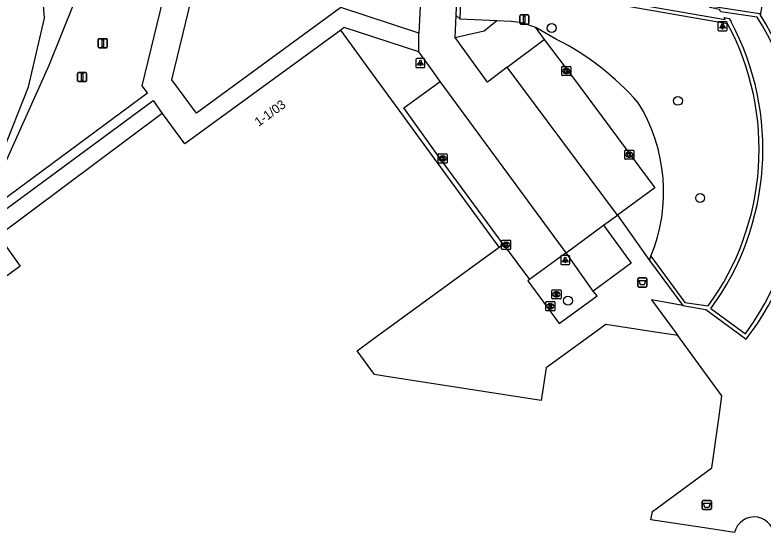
# Model space of a CAD drawing. Extents: x 161094 to 161705, y 379509 to 380907.
# Drawn here: x 161257.9 to 161340, y 380818.7 to 380876.1 of the extents above; entities that cross this region are included whole.
import ezdxf

# ---------------------------------------------------------------- set-up
doc = ezdxf.new("R2010")
doc.units = 0
for name, color, linetype in [('IMGEO_Afvalbak', 7, 'Continuous'), ('IMGEO_Boom', 7, 'Continuous'), ('IMGEO_Groenvoorziening', 7, 'Continuous'), ('IMGEO_Kolk', 7, 'Continuous'), ('IMGEO_Lichtpunt', 7, 'Continuous'), ('IMGEO_Muur', 7, 'Continuous'), ('IMGEO_Pand', 7, 'Continuous'), ('IMGEO_Pand_nummerreeks', 7, 'Continuous'), ('IMGEO_Parkeervlak_open', 7, 'Continuous'), ('IMGEO_Rijbaan_lokaal_open', 7, 'Continuous'), ('IMGEO_Rioolput', 7, 'Continuous'), ('IMGEO_Verkeersbordpaal', 7, 'Continuous'), ('IMGEO_Vlaggenmast', 7, 'Continuous'), ('IMGEO_Voetpad_open', 7, 'Continuous'), ('IMGEO_Waterloop', 7, 'Continuous')]:
    doc.layers.add(name, color=color, linetype=linetype)

msp = doc.modelspace()

# ---------------------------------------------------------------- linework, layer by layer
at = {"layer": 'IMGEO_Afvalbak'}
for p, q in [((161326.239, 380846.413), (161326.239, 380847.213)), ((161326.239, 380847.213), (161326.239, 380846.413)), ((161326.339, 380847.313), (161327.129, 380847.313)), ((161327.129, 380847.313), (161326.339, 380847.313)), ((161327.229, 380847.213), (161327.229, 380846.413)), ((161327.229, 380846.413), (161327.229, 380847.213)), ((161327.129, 380846.313), (161326.339, 380846.313)), ((161326.339, 380846.313), (161327.129, 380846.313)), ((161333.41, 380822.905), (161334.2, 380822.905)), ((161334.2, 380822.905), (161333.41, 380822.905)), ((161333.31, 380822.005), (161333.31, 380822.805)), ((161333.31, 380822.805), (161333.31, 380822.005)), ((161334.3, 380822.805), (161334.3, 380822.005)), ((161334.3, 380822.005), (161334.3, 380822.805)), ((161334.2, 380821.905), (161333.41, 380821.905)), ((161333.41, 380821.905), (161334.2, 380821.905))]:
    msp.add_line(p, q, dxfattribs=at)
for points in [[(161326.382, 380847.027), (161327.086, 380847.027), (161326.937, 380846.557), (161326.531, 380846.557), (161326.382, 380847.027)], [(161333.453, 380822.619), (161334.157, 380822.619), (161334.008, 380822.149), (161333.602, 380822.149), (161333.453, 380822.619)]]:
    msp.add_lwpolyline(points, dxfattribs=at)
for centre, start, end in [((161326.339, 380847.213), 90, 180), ((161326.339, 380847.213), 90, 180), ((161327.129, 380847.213), 0, 90), ((161327.129, 380847.213), 360, 90), ((161326.339, 380846.413), 180, 270), ((161326.339, 380846.413), 180, 270), ((161327.129, 380846.413), 270, 0), ((161327.129, 380846.413), 270, 0), ((161333.41, 380822.805), 90, 180), ((161333.41, 380822.805), 90, 180), ((161334.2, 380822.805), 0, 90), ((161334.2, 380822.805), 360, 90), ((161333.41, 380822.005), 180, 270), ((161333.41, 380822.005), 180, 270), ((161334.2, 380822.005), 270, 0), ((161334.2, 380822.005), 270, 0)]:
    msp.add_arc(centre, 0.1, start, end, dxfattribs=at)
at = {"layer": 'IMGEO_Boom'}
for centre in [(161316.783, 380874.712), (161330.632, 380866.728), (161333.071, 380856.073), (161318.568, 380844.809)]:
    msp.add_circle(centre, 0.489, dxfattribs=at)
at = {"layer": 'IMGEO_Groenvoorziening'}
for points in [[(161247.675, 380847.406), (161250.983, 380852.169), (161256.051, 380858.263), (161261.626, 380870.653), (161264.334, 380877.374), (161264.808, 380880.411), (161265.377, 380888.088)], [(161317.318, 380873.469), (161314.974, 380874.798)]]:
    msp.add_lwpolyline(points, dxfattribs=at)
for centre, radius, start, end in [((161303.829, 380846.829), 29.861, 41.23675, 63.14524), ((161310.537, 380856.742), 18.531, 337.61276, 31.81759)]:
    msp.add_arc(centre, radius, start, end, dxfattribs=at)
at = {"layer": 'IMGEO_Kolk'}
for p, q in [((161317.881, 380869.578), (161317.881, 380870.43)), ((161317.956, 380870.504), (161318.808, 380870.504)), ((161318.882, 380870.43), (161318.882, 380869.578)), ((161318.392, 380869.724), (161318.367, 380869.724)), ((161318.369, 380870.284), (161318.394, 380870.284)), ((161318.808, 380869.504), (161317.956, 380869.504)), ((161304.313, 380859.983), (161304.313, 380860.835)), ((161304.388, 380860.909), (161305.24, 380860.909)), ((161304.801, 380860.689), (161304.826, 380860.689)), ((161305.314, 380860.835), (161305.314, 380859.983)), ((161324.793, 380860.399), (161324.793, 380861.251)), ((161324.868, 380861.325), (161325.72, 380861.325)), ((161325.281, 380861.105), (161325.306, 380861.105)), ((161325.794, 380861.251), (161325.794, 380860.399)), ((161305.24, 380859.909), (161304.388, 380859.909)), ((161304.824, 380860.129), (161304.799, 380860.129)), ((161325.72, 380860.325), (161324.868, 380860.325)), ((161325.304, 380860.545), (161325.279, 380860.545)), ((161311.279, 380850.515), (161311.279, 380851.367)), ((161311.354, 380851.441), (161312.206, 380851.441)), ((161311.767, 380851.221), (161311.792, 380851.221)), ((161312.28, 380851.367), (161312.28, 380850.515)), ((161312.206, 380850.441), (161311.354, 380850.441)), ((161311.79, 380850.661), (161311.765, 380850.661))]:
    msp.add_line(p, q, dxfattribs=at)
for points in [[(161317.881, 380869.578), (161317.881, 380870.43)], [(161317.956, 380870.504), (161318.808, 380870.504)], [(161318.882, 380870.43), (161318.882, 380869.578)], [(161318.202, 380870.204), (161318.325, 380870.204), (161318.325, 380870.053), (161318.455, 380870.204), (161318.619, 380870.204), (161318.473, 380870.053), (161318.626, 380869.804), (161318.474, 380869.804), (161318.389, 380869.968), (161318.325, 380869.901), (161318.325, 380869.804), (161318.202, 380869.804), (161318.202, 380870.204)], [(161318.808, 380869.504), (161317.956, 380869.504)], [(161304.313, 380859.983), (161304.313, 380860.835)], [(161304.388, 380860.909), (161305.24, 380860.909)], [(161304.634, 380860.609), (161304.757, 380860.609), (161304.757, 380860.458), (161304.887, 380860.609), (161305.051, 380860.609), (161304.905, 380860.458), (161305.058, 380860.209), (161304.906, 380860.209), (161304.821, 380860.373), (161304.757, 380860.306), (161304.757, 380860.209), (161304.634, 380860.209), (161304.634, 380860.609)], [(161305.314, 380860.835), (161305.314, 380859.983)], [(161324.793, 380860.399), (161324.793, 380861.251)], [(161324.868, 380861.325), (161325.72, 380861.325)], [(161325.114, 380861.025), (161325.237, 380861.025), (161325.237, 380860.874), (161325.367, 380861.025), (161325.531, 380861.025), (161325.385, 380860.874), (161325.538, 380860.625), (161325.386, 380860.625), (161325.301, 380860.789), (161325.237, 380860.722), (161325.237, 380860.625), (161325.114, 380860.625), (161325.114, 380861.025)], [(161325.794, 380861.251), (161325.794, 380860.399)], [(161305.24, 380859.909), (161304.388, 380859.909)], [(161325.72, 380860.325), (161324.868, 380860.325)], [(161311.279, 380850.515), (161311.279, 380851.367)], [(161311.354, 380851.441), (161312.206, 380851.441)], [(161311.6, 380851.141), (161311.723, 380851.141), (161311.723, 380850.99), (161311.853, 380851.141), (161312.017, 380851.141), (161311.871, 380850.99), (161312.024, 380850.741), (161311.872, 380850.741), (161311.787, 380850.905), (161311.723, 380850.838), (161311.723, 380850.741), (161311.6, 380850.741), (161311.6, 380851.141)], [(161312.28, 380851.367), (161312.28, 380850.515)], [(161312.206, 380850.441), (161311.354, 380850.441)]]:
    msp.add_lwpolyline(points, dxfattribs=at)
for centre, start, end in [((161317.958, 380870.428), 91.55205, 178.44795), ((161317.958, 380870.428), 91.55205, 178.44795), ((161318.806, 380870.428), 1.55205, 88.44795), ((161318.806, 380870.428), 1.55205, 88.44795), ((161317.958, 380869.58), 181.55205, 268.44795), ((161317.958, 380869.58), 181.55205, 268.44795), ((161318.806, 380869.58), 271.55205, 358.44795), ((161318.806, 380869.58), 271.55205, 358.44795), ((161304.39, 380860.833), 91.55205, 178.44795), ((161304.39, 380860.833), 91.55205, 178.44795), ((161305.238, 380860.833), 1.55205, 88.44795), ((161305.238, 380860.833), 1.55205, 88.44795), ((161324.87, 380861.249), 91.55205, 178.44795), ((161324.87, 380861.249), 91.55205, 178.44795), ((161325.718, 380861.249), 1.55205, 88.44795), ((161325.718, 380861.249), 1.55205, 88.44795), ((161304.39, 380859.985), 181.55205, 268.44795), ((161304.39, 380859.985), 181.55205, 268.44795), ((161305.238, 380859.985), 271.55205, 358.44795), ((161305.238, 380859.985), 271.55205, 358.44795), ((161324.87, 380860.401), 181.55205, 268.44795), ((161324.87, 380860.401), 181.55205, 268.44795), ((161325.718, 380860.401), 271.55205, 358.44795), ((161325.718, 380860.401), 271.55205, 358.44795), ((161311.356, 380851.365), 91.55205, 178.44795), ((161311.356, 380851.365), 91.55205, 178.44795), ((161312.204, 380851.365), 1.55205, 88.44795), ((161312.204, 380851.365), 1.55205, 88.44795), ((161311.356, 380850.517), 181.55205, 268.44795), ((161311.356, 380850.517), 181.55205, 268.44795), ((161312.204, 380850.517), 271.55205, 358.44795), ((161312.204, 380850.517), 271.55205, 358.44795)]:
    msp.add_arc(centre, 0.0765, start, end, dxfattribs=at)
for centre, major_axis, ratio, start_param, end_param in [((161318.368, 380870.004), (-0.387, 0.002), 0.722429, 4.712389, 7.853982), ((161318.393, 380870.004), (-0.39, 0.002), 0.717154, 1.570796, 4.712389), ((161304.8, 380860.409), (-0.387, 0.002), 0.722429, 4.712389, 7.853982), ((161304.825, 380860.409), (-0.39, 0.002), 0.717154, 1.570796, 4.712389), ((161325.28, 380860.825), (-0.387, 0.002), 0.722429, 4.712389, 7.853982), ((161325.305, 380860.825), (-0.39, 0.002), 0.717154, 1.570796, 4.712389), ((161311.766, 380850.941), (-0.387, 0.002), 0.722429, 4.712389, 7.853982), ((161311.791, 380850.941), (-0.39, 0.002), 0.717154, 1.570796, 4.712389)]:
    msp.add_ellipse(centre, major_axis=major_axis, ratio=ratio, start_param=start_param, end_param=end_param, dxfattribs=at)
at = {"layer": 'IMGEO_Lichtpunt'}
for p, q in [((161335.928, 380875.411), (161335.12, 380875.411)), ((161335.928, 380875.411), (161335.12, 380875.411)), ((161335.026, 380875.316), (161335.026, 380874.509)), ((161335.026, 380875.316), (161335.026, 380874.509)), ((161336.022, 380874.509), (161336.022, 380875.316)), ((161336.022, 380874.509), (161336.022, 380875.316)), ((161335.12, 380874.415), (161335.928, 380874.415)), ((161335.12, 380874.415), (161335.928, 380874.415)), ((161301.874, 380871.278), (161301.874, 380870.471)), ((161301.874, 380871.278), (161301.874, 380870.471)), ((161302.776, 380871.373), (161301.968, 380871.373)), ((161302.776, 380871.373), (161301.968, 380871.373)), ((161302.87, 380870.471), (161302.87, 380871.278)), ((161302.87, 380870.471), (161302.87, 380871.278)), ((161301.968, 380870.377), (161302.776, 380870.377)), ((161301.968, 380870.377), (161302.776, 380870.377)), ((161317.768, 380849.682), (161317.768, 380848.875)), ((161317.768, 380849.682), (161317.768, 380848.875)), ((161318.67, 380849.777), (161317.862, 380849.777)), ((161318.67, 380849.777), (161317.862, 380849.777)), ((161318.764, 380848.875), (161318.764, 380849.682)), ((161318.764, 380848.875), (161318.764, 380849.682)), ((161317.862, 380848.781), (161318.67, 380848.781)), ((161317.862, 380848.781), (161318.67, 380848.781))]:
    msp.add_line(p, q, dxfattribs=at)
for points in [[(161335.4, 380874.98), (161335.439, 380874.952), (161335.251, 380874.69), (161335.213, 380874.717), (161335.4, 380874.98)], [(161335.502, 380874.932), (161335.549, 380874.932), (161335.549, 380874.61), (161335.502, 380874.61), (161335.502, 380874.932)], [(161335.612, 380874.952), (161335.65, 380874.979), (161335.837, 380874.717), (161335.798, 380874.689), (161335.612, 380874.952)], [(161302.248, 380870.942), (161302.287, 380870.914), (161302.099, 380870.652), (161302.061, 380870.679), (161302.248, 380870.942)], [(161302.35, 380870.894), (161302.397, 380870.894), (161302.397, 380870.572), (161302.35, 380870.572), (161302.35, 380870.894)], [(161302.46, 380870.914), (161302.498, 380870.941), (161302.685, 380870.679), (161302.646, 380870.651), (161302.46, 380870.914)], [(161318.142, 380849.346), (161318.181, 380849.318), (161317.993, 380849.056), (161317.955, 380849.083), (161318.142, 380849.346)], [(161318.244, 380849.298), (161318.291, 380849.298), (161318.291, 380848.976), (161318.244, 380848.976), (161318.244, 380849.298)], [(161318.354, 380849.318), (161318.392, 380849.345), (161318.579, 380849.083), (161318.54, 380849.055), (161318.354, 380849.318)]]:
    msp.add_lwpolyline(points, dxfattribs=at)
for centre in [(161335.525, 380875.114), (161302.373, 380871.076), (161318.267, 380849.48)]:
    msp.add_circle(centre, 0.0994, dxfattribs=at)
for centre, start, end in [((161335.12, 380875.316), 90, 180), ((161335.12, 380875.316), 90, 180), ((161335.928, 380875.316), 0, 90), ((161335.928, 380875.316), 0, 90), ((161335.12, 380874.509), 180, 270), ((161335.12, 380874.509), 180, 270), ((161335.928, 380874.509), 270, 0), ((161335.928, 380874.509), 270, 360), ((161301.968, 380871.278), 90, 180), ((161301.968, 380871.278), 90, 180), ((161302.776, 380871.278), 0, 90), ((161302.776, 380871.278), 0, 90), ((161301.968, 380870.471), 180, 270), ((161301.968, 380870.471), 180, 270), ((161302.776, 380870.471), 270, 0), ((161302.776, 380870.471), 270, 360), ((161317.862, 380849.682), 90, 180), ((161317.862, 380849.682), 90, 180), ((161318.67, 380849.682), 0, 90), ((161318.67, 380849.682), 0, 90), ((161317.862, 380848.875), 180, 270), ((161317.862, 380848.875), 180, 270), ((161318.67, 380848.875), 270, 0), ((161318.67, 380848.875), 270, 360)]:
    msp.add_arc(centre, 0.0946, start, end, dxfattribs=at)
at = {"layer": 'IMGEO_Muur'}
for points in [[(161306.292, 380876.085), (161306.491, 380880.768)], [(161306.491, 380880.768), (161335.834, 380875.644), (161335.707, 380875.861), (161336.242, 380875.775), (161336.471, 380875.384)], [(161336.089, 380875.176), (161306.872, 380880.312), (161306.694, 380875.729)], [(161339.327, 380875.911), (161335.345, 380876.499), (161335.189, 380876.739), (161334.122, 380876.951), (161334.149, 380877.149)], [(161334.149, 380877.149), (161339.598, 380876.315), (161339.698, 380876.139)], [(161306.292, 380876.085), (161306.694, 380875.729)], [(161327.526, 380849.234), (161327.672, 380849.684)], [(161327.526, 380849.234), (161331.183, 380844.292)], [(161327.672, 380849.684), (161331.402, 380844.627), (161333.951, 380844.232)], [(161331.183, 380844.292), (161333.696, 380843.835), (161338.134, 380840.611), (161339.389, 380842.344)], [(161334.256, 380843.966), (161338.044, 380841.191), (161338.993, 380842.577)]]:
    msp.add_lwpolyline(points, dxfattribs=at)
for centre, radius, start, end in [((161310.336, 380861.439), 29.623, 323.85249, 28.08204), ((161313.163, 380859.504), 30.882, 326.76115, 32.0907), ((161313.219, 380859.482), 31.283, 326.78041, 32.17187), ((161310.355, 380861.408), 29.186, 323.94831, 28.14683)]:
    msp.add_arc(centre, radius, start, end, dxfattribs=at)
at = {"layer": 'IMGEO_Pand'}
for points in [[(161293.631, 380874.499), (161279.082, 380863.878), (161276.517, 380862.005), (161274.07, 380865.356), (161274.053, 380865.344)], [(161311.016, 380850.691), (161301.815, 380863.291), (161300.061, 380865.693), (161297.65, 380868.996), (161293.631, 380874.499)], [(161274.053, 380865.344), (161256.041, 380851.928), (161258.47, 380848.601), (161250.895, 380843.069)], [(161330.618, 380840.979), (161328.148, 380841.364), (161322.714, 380842.211), (161316.181, 380837.441), (161315.622, 380833.857), (161298.659, 380836.502), (161297.352, 380836.706), (161295.443, 380839.321), (161297.016, 380840.47), (161311.016, 380850.691)], [(161336.848, 380819.378), (161334.032, 380819.813), (161327.677, 380820.795), (161327.827, 380821.683), (161334.36, 380826.485), (161335.14, 380832.159), (161335.444, 380834.369), (161330.618, 380840.979)]]:
    msp.add_lwpolyline(points, dxfattribs=at)
msp.add_arc((161339.004, 380818.89), 2.21, 354.38515, 167.24963, dxfattribs=at)
at = {"layer": 'IMGEO_Parkeervlak_open'}
for points in [[(161315.969, 380873.472), (161319.059, 380869.353), (161328.094, 380857.194), (161323.99, 380854.186)], [(161311.468, 380851.012), (161304.146, 380860.954), (161300.557, 380865.96), (161304.557, 380868.865)], [(161318.367, 380850.08), (161314.33, 380847.126)], [(161321.349, 380845.873), (161318.367, 380850.08)]]:
    msp.add_lwpolyline(points, dxfattribs=at)
at = {"layer": 'IMGEO_Rijbaan_lokaal_open'}
for points in [[(161302.568, 380881.457), (161302.206, 380874.169)], [(161339.698, 380876.139), (161339.865, 380877.163)], [(161306.191, 380873.695), (161306.292, 380876.085)], [(161302.186, 380872.114), (161302.206, 380874.169)], [(161311.914, 380870.415), (161309.729, 380868.769), (161306.191, 380873.695)], [(161304.557, 380868.865), (161303.657, 380870.085), (161302.186, 380872.114)], [(161323.99, 380854.186), (161311.914, 380870.415)], [(161318.367, 380850.08), (161304.557, 380868.865)], [(161322.471, 380853.084), (161323.99, 380854.186)], [(161318.367, 380850.08), (161322.471, 380853.084)], [(161331.183, 380844.292), (161327.742, 380844.918), (161330.618, 380840.979)]]:
    msp.add_lwpolyline(points, dxfattribs=at)
at = {"layer": 'IMGEO_Rioolput'}
for p, q in [((161316.804, 380845.077), (161316.804, 380845.929)), ((161316.879, 380846.003), (161317.731, 380846.003)), ((161317.805, 380845.929), (161317.805, 380845.077)), ((161317.731, 380845.003), (161316.879, 380845.003)), ((161317.315, 380845.223), (161317.29, 380845.223)), ((161317.292, 380845.783), (161317.317, 380845.783)), ((161316.139, 380843.782), (161316.139, 380844.634)), ((161316.214, 380844.708), (161317.066, 380844.708)), ((161316.627, 380844.488), (161316.652, 380844.488)), ((161317.14, 380844.634), (161317.14, 380843.782)), ((161317.066, 380843.708), (161316.214, 380843.708)), ((161316.65, 380843.928), (161316.625, 380843.928))]:
    msp.add_line(p, q, dxfattribs=at)
for points in [[(161316.804, 380845.077), (161316.804, 380845.929)], [(161316.879, 380846.003), (161317.731, 380846.003)], [(161317.805, 380845.929), (161317.805, 380845.077)], [(161317.731, 380845.003), (161316.879, 380845.003)], [(161317.393, 380845.701), (161317.141, 380845.703), (161317.141, 380845.303)], [(161317.141, 380845.303), (161317.265, 380845.303), (161317.265, 380845.465), (161317.276, 380845.465)], [(161317.319, 380845.622), (161317.265, 380845.622), (161317.265, 380845.541)], [(161317.265, 380845.541), (161317.317, 380845.541)], [(161317.323, 380845.436), (161317.394, 380845.303), (161317.534, 380845.303), (161317.469, 380845.429)], [(161316.139, 380843.782), (161316.139, 380844.634)], [(161316.214, 380844.708), (161317.066, 380844.708)], [(161316.728, 380844.406), (161316.476, 380844.408), (161316.476, 380844.008)], [(161316.476, 380844.008), (161316.6, 380844.008), (161316.6, 380844.17), (161316.611, 380844.17)], [(161316.654, 380844.327), (161316.6, 380844.327), (161316.6, 380844.246)], [(161316.6, 380844.246), (161316.652, 380844.246)], [(161317.14, 380844.634), (161317.14, 380843.782)], [(161317.066, 380843.708), (161316.214, 380843.708)], [(161316.658, 380844.141), (161316.729, 380844.008), (161316.869, 380844.008), (161316.804, 380844.134)]]:
    msp.add_lwpolyline(points, dxfattribs=at)
for centre, radius, start, end in [((161316.881, 380845.927), 0.0765, 91.55205, 178.44795), ((161316.881, 380845.927), 0.0765, 91.55205, 178.44795), ((161317.729, 380845.927), 0.0765, 1.55205, 88.44795), ((161317.729, 380845.927), 0.0765, 1.55205, 88.44795), ((161316.881, 380845.079), 0.0765, 181.55205, 268.44795), ((161316.881, 380845.079), 0.0765, 181.55205, 268.44795), ((161317.275, 380845.412), 0.0533, 26.02933, 88.69889), ((161317.301, 380845.73), 0.19, 274.7715, 282.96867), ((161317.325, 380845.526), 0.0964, 77.00612, 93.18647), ((161317.339, 380845.583), 0.0378, 276.66336, 79.67722), ((161317.392, 380845.591), 0.109, 350.36119, 89.41601), ((161317.39, 380845.591), 0.112, 277.58423, 350.98172), ((161317.374, 380845.376), 0.108, 29.51342, 73.79051), ((161317.729, 380845.079), 0.0765, 271.55205, 358.44795), ((161317.729, 380845.079), 0.0765, 271.55205, 358.44795), ((161316.216, 380844.632), 0.0765, 91.55205, 178.44795), ((161316.216, 380844.632), 0.0765, 91.55205, 178.44795), ((161316.61, 380844.117), 0.0533, 26.02933, 88.69889), ((161316.636, 380844.435), 0.19, 274.7715, 282.96867), ((161316.66, 380844.231), 0.0964, 77.00612, 93.18647), ((161316.674, 380844.288), 0.0378, 276.66336, 79.67722), ((161316.727, 380844.296), 0.109, 350.36119, 89.41601), ((161316.725, 380844.296), 0.112, 277.58423, 350.98172), ((161316.709, 380844.081), 0.108, 29.51342, 73.79051), ((161317.064, 380844.632), 0.0765, 1.55205, 88.44795), ((161317.064, 380844.632), 0.0765, 1.55205, 88.44795), ((161316.216, 380843.784), 0.0765, 181.55205, 268.44795), ((161316.216, 380843.784), 0.0765, 181.55205, 268.44795), ((161317.064, 380843.784), 0.0765, 271.55205, 358.44795), ((161317.064, 380843.784), 0.0765, 271.55205, 358.44795)]:
    msp.add_arc(centre, radius, start, end, dxfattribs=at)
for centre, major_axis, ratio, start_param, end_param in [((161317.291, 380845.503), (-0.387, 0.002), 0.722429, 4.712389, 7.853982), ((161317.316, 380845.503), (-0.39, 0.002), 0.717154, 1.570796, 4.712389), ((161316.626, 380844.208), (-0.387, 0.002), 0.722429, 4.712389, 7.853982), ((161316.651, 380844.208), (-0.39, 0.002), 0.717154, 1.570796, 4.712389)]:
    msp.add_ellipse(centre, major_axis=major_axis, ratio=ratio, start_param=start_param, end_param=end_param, dxfattribs=at)
at = {"layer": 'IMGEO_Verkeersbordpaal'}
for p, q in [((161313.278, 380875.25), (161313.278, 380876.05)), ((161313.278, 380876.05), (161313.278, 380875.25)), ((161313.378, 380876.15), (161314.168, 380876.15)), ((161314.168, 380876.15), (161313.378, 380876.15)), ((161314.268, 380876.05), (161314.268, 380875.25)), ((161314.268, 380875.25), (161314.268, 380876.05)), ((161314.168, 380875.15), (161313.378, 380875.15)), ((161313.378, 380875.15), (161314.168, 380875.15))]:
    msp.add_line(p, q, dxfattribs=at)
msp.add_lwpolyline([(161313.698, 380876.025), (161313.848, 380876.025), (161313.848, 380875.275), (161313.698, 380875.275), (161313.698, 380876.025)], dxfattribs=at)
for centre, start, end in [((161313.378, 380876.05), 90, 180), ((161313.378, 380876.05), 90, 180), ((161314.168, 380876.05), 0, 90), ((161314.168, 380876.05), 360, 90), ((161313.378, 380875.25), 180, 270), ((161313.378, 380875.25), 180, 270), ((161314.168, 380875.25), 270, 0), ((161314.168, 380875.25), 270, 0)]:
    msp.add_arc(centre, 0.1, start, end, dxfattribs=at)
at = {"layer": 'IMGEO_Vlaggenmast'}
for p, q in [((161267.03, 380872.645), (161267.03, 380873.445)), ((161267.03, 380873.445), (161267.03, 380872.645)), ((161267.13, 380873.545), (161267.92, 380873.545)), ((161267.92, 380873.545), (161267.13, 380873.545)), ((161268.02, 380873.445), (161268.02, 380872.645)), ((161268.02, 380872.645), (161268.02, 380873.445)), ((161267.92, 380872.545), (161267.13, 380872.545)), ((161267.13, 380872.545), (161267.92, 380872.545)), ((161264.76, 380868.943), (161264.76, 380869.743)), ((161264.76, 380869.743), (161264.76, 380868.943)), ((161264.86, 380869.843), (161265.65, 380869.843)), ((161265.65, 380869.843), (161264.86, 380869.843)), ((161265.75, 380869.743), (161265.75, 380868.943)), ((161265.75, 380868.943), (161265.75, 380869.743)), ((161265.65, 380868.843), (161264.86, 380868.843)), ((161264.86, 380868.843), (161265.65, 380868.843))]:
    msp.add_line(p, q, dxfattribs=at)
for points in [[(161267.45, 380873.42), (161267.6, 380873.42), (161267.6, 380872.67), (161267.45, 380872.67), (161267.45, 380873.42)], [(161265.18, 380869.718), (161265.33, 380869.718), (161265.33, 380868.968), (161265.18, 380868.968), (161265.18, 380869.718)]]:
    msp.add_lwpolyline(points, dxfattribs=at)
for centre, start, end in [((161267.13, 380873.445), 90, 180), ((161267.13, 380873.445), 90, 180), ((161267.92, 380873.445), 0, 90), ((161267.92, 380873.445), 360, 90), ((161267.13, 380872.645), 180, 270), ((161267.13, 380872.645), 180, 270), ((161267.92, 380872.645), 270, 0), ((161267.92, 380872.645), 270, 0), ((161264.86, 380869.743), 90, 180), ((161264.86, 380869.743), 90, 180), ((161265.65, 380869.743), 0, 90), ((161265.65, 380869.743), 360, 90), ((161264.86, 380868.943), 180, 270), ((161264.86, 380868.943), 180, 270), ((161265.65, 380868.943), 270, 0), ((161265.65, 380868.943), 270, 0)]:
    msp.add_arc(centre, 0.1, start, end, dxfattribs=at)
at = {"layer": 'IMGEO_Voetpad_open'}
for points in [[(161250.213, 380843.988), (161254.232, 380854.161), (161272.446, 380867.595), (161271.851, 380868.388), (161276.152, 380886.159)], [(161302.206, 380874.169), (161293.658, 380876.966), (161277.805, 380865.373), (161275.111, 380869.035), (161279.123, 380885.638)], [(161306.191, 380873.695), (161306.619, 380873.79), (161309.37, 380874.418), (161310.769, 380875.535)], [(161306.694, 380875.729), (161310.769, 380875.535)], [(161310.769, 380875.535), (161312.325, 380875.461), (161313.26, 380875.349), (161314.166, 380875.118), (161314.974, 380874.798)], [(161302.186, 380872.114), (161293.999, 380874.768), (161293.631, 380874.499)], [(161314.974, 380874.798), (161315.969, 380873.472)], [(161311.914, 380870.415), (161315.969, 380873.472)], [(161250.895, 380843.069), (161255.03, 380853.506), (161273.043, 380866.778), (161274.053, 380865.344)], [(161323.99, 380854.186), (161327.526, 380849.234)], [(161322.471, 380853.084), (161325.497, 380848.94), (161321.349, 380845.873)], [(161311.016, 380850.691), (161311.468, 380851.012)], [(161311.468, 380851.012), (161314.33, 380847.126)], [(161314.33, 380847.126), (161314.157, 380846.988), (161317.594, 380842.294), (161321.754, 380845.364), (161321.349, 380845.873)]]:
    msp.add_lwpolyline(points, dxfattribs=at)
at = {"layer": 'IMGEO_Waterloop'}
msp.add_lwpolyline([(161247.017, 380848.292), (161255.041, 380858.355), (161256.486, 380860.952), (161259.37, 380868.262), (161261.146, 380875.809), (161260.902, 380878.736), (161261.788, 380880.822), (161261.766, 380882.473), (161262.514, 380886.927), (161261.741, 380888.03), (161261.675, 380889.329), (161262.072, 380890.254), (161263.15, 380891.685), (161263.465, 380894.284), (161263.465, 380897.789), (161263.502, 380898.033), (161263.821, 380900.638), (161264.167, 380903.399), (161264.517, 380906.196), (161264.517, 380906.196)], dxfattribs=at)

# ---------------------------------------------------------------- texts
at = {"layer": 'IMGEO_Pand_nummerreeks'}
msp.add_text('1-1/03', height=1, rotation=36.13072, dxfattribs=at).set_placement((161284.639, 380863.874))

doc.saveas('drawing.dxf')
